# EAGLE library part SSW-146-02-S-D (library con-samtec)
THROUGH-HOLE .025" SQ POST SOCKET Source: Samtec SSW.pdf
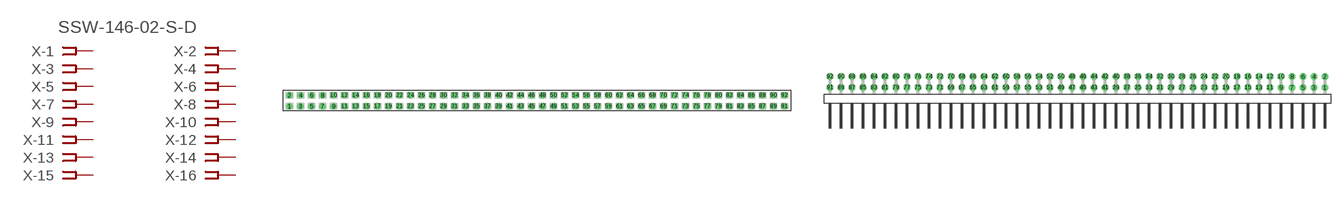
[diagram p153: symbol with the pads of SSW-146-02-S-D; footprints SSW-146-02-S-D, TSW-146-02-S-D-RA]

Designator prefix X; gates -1=FPINV -2=FPIN -3=FPIN -4=FPIN -5=FPIN -6=FPIN -7=FPIN -8=FPIN -9=FPIN -10=FPIN -11=FPIN -12=FPIN -13=FPIN -14=FPIN -15=FPIN -16=FPIN -17=FPIN -18=FPIN -19=FPIN -20=FPIN -21=FPIN -22=FPIN -23=FPIN -24=FPIN -25=FPIN -26=FPIN -27=FPIN -28=FPIN -29=FPIN -30=FPIN -31=FPIN -32=FPIN -33=FPIN -34=FPIN -35=FPIN -36=FPIN -37=FPIN -38=FPIN -39=FPIN -40=FPIN -41=FPIN -42=FPIN -43=FPIN -44=FPIN -45=FPIN -46=FPIN -47=FPIN -48=FPIN -49=FPIN -50=FPIN -51=FPIN -52=FPIN -53=FPIN -54=FPIN -55=FPIN -56=FPIN -57=FPIN -58=FPIN -59=FPIN -60=FPIN -61=FPIN -62=FPIN -63=FPIN -64=FPIN -65=FPIN -66=FPIN -67=FPIN -68=FPIN -69=FPIN -70=FPIN -71=FPIN -72=FPIN -73=FPIN -74=FPIN -75=FPIN -76=FPIN -77=FPIN -78=FPIN -79=FPIN -80=FPIN -81=FPIN -82=FPIN -83=FPIN -84=FPIN -85=FPIN -86=FPIN -87=FPIN -88=FPIN -89=FPIN -90=FPIN -91=FPIN -92=FPIN

## SSW-146-02-S-D (OC_FARNELL: unknown; OC_NEWARK: unknown)  [SSW-146-02-S-D]
1  -1:1  pas
2  -2:1  pas
3  -3:1  pas
4  -4:1  pas
5  -5:1  pas
6  -6:1  pas
7  -7:1  pas
8  -8:1  pas
9  -9:1  pas
10  -10:1  pas
11  -11:1  pas
12  -12:1  pas
13  -13:1  pas
14  -14:1  pas
15  -15:1  pas
16  -16:1  pas
17  -17:1  pas
18  -18:1  pas
19  -19:1  pas
20  -20:1  pas
21  -21:1  pas
22  -22:1  pas
23  -23:1  pas
24  -24:1  pas
25  -25:1  pas
26  -26:1  pas
27  -27:1  pas
28  -28:1  pas
29  -29:1  pas
30  -30:1  pas
31  -31:1  pas
32  -32:1  pas
33  -33:1  pas
34  -34:1  pas
35  -35:1  pas
36  -36:1  pas
37  -37:1  pas
38  -38:1  pas
39  -39:1  pas
40  -40:1  pas
41  -41:1  pas
42  -42:1  pas
43  -43:1  pas
44  -44:1  pas
45  -45:1  pas
46  -46:1  pas
47  -47:1  pas
48  -48:1  pas
49  -49:1  pas
50  -50:1  pas
51  -51:1  pas
52  -52:1  pas
53  -53:1  pas
54  -54:1  pas
55  -55:1  pas
56  -56:1  pas
57  -57:1  pas
58  -58:1  pas
59  -59:1  pas
60  -60:1  pas
61  -61:1  pas
62  -62:1  pas
63  -63:1  pas
64  -64:1  pas
65  -65:1  pas
66  -66:1  pas
67  -67:1  pas
68  -68:1  pas
69  -69:1  pas
70  -70:1  pas
71  -71:1  pas
72  -72:1  pas
73  -73:1  pas
74  -74:1  pas
75  -75:1  pas
76  -76:1  pas
77  -77:1  pas
78  -78:1  pas
79  -79:1  pas
80  -80:1  pas
81  -81:1  pas
82  -82:1  pas
83  -83:1  pas
84  -84:1  pas
85  -85:1  pas
86  -86:1  pas
87  -87:1  pas
88  -88:1  pas
89  -89:1  pas
90  -90:1  pas
91  -91:1  pas
92  -92:1  pas

## SSW-146-02-S-D-RA (OC_FARNELL: unknown; OC_NEWARK: unknown)  [TSW-146-02-S-D-RA]
Pads as for SSW-146-02-S-D

## Footprint SSW-146-02-S-D (pad centres in mm)
THROUGH-HOLE .025" SQ POST SOCKET Source: Samtec SSW.pdf
drill 1 pad 1.5 octagon: 1 -57.15,-1.27; 2 -57.15,1.27; 3 -54.61,-1.27; 4 -54.61,1.27; 5 -52.07,-1.27; 6 -52.07,1.27; 7 -49.53,-1.27; 8 -49.53,1.27; 9 -46.99,-1.27; 10 -46.99,1.27; 11 -44.45,-1.27; 12 -44.45,1.27; 13 -41.91,-1.27; 14 -41.91,1.27; 15 -39.37,-1.27; 16 -39.37,1.27; 17 -36.83,-1.27; 18 -36.83,1.27; 19 -34.29,-1.27; 20 -34.29,1.27; 21 -31.75,-1.27; 22 -31.75,1.27; 23 -29.21,-1.27; 24 -29.21,1.27; 25 -26.67,-1.27; 26 -26.67,1.27; 27 -24.13,-1.27; 28 -24.13,1.27; 29 -21.59,-1.27; 30 -21.59,1.27; 31 -19.05,-1.27; 32 -19.05,1.27; 33 -16.51,-1.27; 34 -16.51,1.27; 35 -13.97,-1.27; 36 -13.97,1.27; 37 -11.43,-1.27; 38 -11.43,1.27; 39 -8.89,-1.27; 40 -8.89,1.27; 41 -6.35,-1.27; 42 -6.35,1.27; 43 -3.81,-1.27; 44 -3.81,1.27; 45 -1.27,-1.27; 46 -1.27,1.27; 47 1.27,-1.27; 48 1.27,1.27; 49 3.81,-1.27; 50 3.81,1.27; 51 6.35,-1.27; 52 6.35,1.27; 53 8.89,-1.27; 54 8.89,1.27; 55 11.43,-1.27; 56 11.43,1.27; 57 13.97,-1.27; 58 13.97,1.27; 59 16.51,-1.27; 60 16.51,1.27; 61 19.05,-1.27; 62 19.05,1.27; 63 21.59,-1.27; 64 21.59,1.27; 65 24.13,-1.27; 66 24.13,1.27; 67 26.67,-1.27; 68 26.67,1.27; 69 29.21,-1.27; 70 29.21,1.27; 71 31.75,-1.27; 72 31.75,1.27; 73 34.29,-1.27; 74 34.29,1.27; 75 36.83,-1.27; 76 36.83,1.27; 77 39.37,-1.27; 78 39.37,1.27; 79 41.91,-1.27; 80 41.91,1.27; 81 44.45,-1.27; 82 44.45,1.27; 83 46.99,-1.27; 84 46.99,1.27; 85 49.53,-1.27; 86 49.53,1.27; 87 52.07,-1.27; 88 52.07,1.27; 89 54.61,-1.27; 90 54.61,1.27; 91 57.15,-1.27; 92 57.15,1.27

## Footprint TSW-146-02-S-D-RA (pad centres in mm)
THROUGH-HOLE .025" SQ POST HEADER Source: Samtec TSW.pdf
drill 1 pad 1.5 octagon: 1 57.15,1.524; 2 57.15,4.064; 3 54.61,1.524; 4 54.61,4.064; 5 52.07,1.524; 6 52.07,4.064; 7 49.53,1.524; 8 49.53,4.064; 9 46.99,1.524; 10 46.99,4.064; 11 44.45,1.524; 12 44.45,4.064; 13 41.91,1.524; 14 41.91,4.064; 15 39.37,1.524; 16 39.37,4.064; 17 36.83,1.524; 18 36.83,4.064; 19 34.29,1.524; 20 34.29,4.064; 21 31.75,1.524; 22 31.75,4.064; 23 29.21,1.524; 24 29.21,4.064; 25 26.67,1.524; 26 26.67,4.064; 27 24.13,1.524; 28 24.13,4.064; 29 21.59,1.524; 30 21.59,4.064; 31 19.05,1.524; 32 19.05,4.064; 33 16.51,1.524; 34 16.51,4.064; 35 13.97,1.524; 36 13.97,4.064; 37 11.43,1.524; 38 11.43,4.064; 39 8.89,1.524; 40 8.89,4.064; 41 6.35,1.524; 42 6.35,4.064; 43 3.81,1.524; 44 3.81,4.064; 45 1.27,1.524; 46 1.27,4.064; 47 -1.27,1.524; 48 -1.27,4.064; 49 -3.81,1.524; 50 -3.81,4.064; 51 -6.35,1.524; 52 -6.35,4.064; 53 -8.89,1.524; 54 -8.89,4.064; 55 -11.43,1.524; 56 -11.43,4.064; 57 -13.97,1.524; 58 -13.97,4.064; 59 -16.51,1.524; 60 -16.51,4.064; 61 -19.05,1.524; 62 -19.05,4.064; 63 -21.59,1.524; 64 -21.59,4.064; 65 -24.13,1.524; 66 -24.13,4.064; 67 -26.67,1.524; 68 -26.67,4.064; 69 -29.21,1.524; 70 -29.21,4.064; 71 -31.75,1.524; 72 -31.75,4.064; 73 -34.29,1.524; 74 -34.29,4.064; 75 -36.83,1.524; 76 -36.83,4.064; 77 -39.37,1.524; 78 -39.37,4.064; 79 -41.91,1.524; 80 -41.91,4.064; 81 -44.45,1.524; 82 -44.45,4.064; 83 -46.99,1.524; 84 -46.99,4.064; 85 -49.53,1.524; 86 -49.53,4.064; 87 -52.07,1.524; 88 -52.07,4.064; 89 -54.61,1.524; 90 -54.61,4.064; 91 -57.15,1.524; 92 -57.15,4.064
